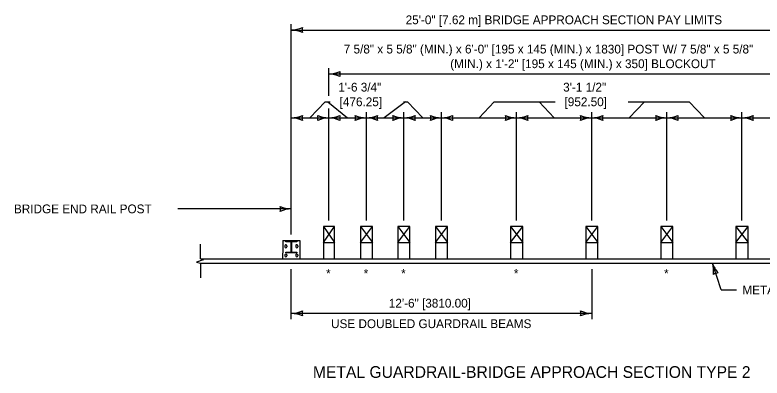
# Model space of a CAD drawing. Extents: x 49991.4 to 50021, y 49987.6 to 50011.4.
# Drawn here: x 50008.83 to 50013.94, y 49992.32 to 49994.8 of the extents above; entities that cross this region are included whole.
import ezdxf

# ---------------------------------------------------------------- set-up
doc = ezdxf.new("R2010")
doc.units = 0
for name, color, linetype in [('Level 1', 7, 'Continuous'), ('Level 2', 7, 'Continuous'), ('Level 3', 7, 'Continuous'), ('Level 6', 7, 'Continuous')]:
    doc.layers.add(name, color=color, linetype=linetype)

msp = doc.modelspace()

# ---------------------------------------------------------------- linework, layer by layer
at = {"layer": 'Level 1'}
for p, q in [((50011.0154, 49993.3576), (50010.9402, 49993.3576)), ((50010.9402, 49993.3576), (50010.9402, 49993.1371)), ((50010.9402, 49993.2474), (50011.0154, 49993.3576)), ((50010.9402, 49993.3576), (50011.0154, 49993.2474)), ((50011.0154, 49993.1371), (50011.0154, 49993.3576)), ((50011.2757, 49993.3576), (50011.1931, 49993.3576)), ((50011.1931, 49993.3576), (50011.1931, 49993.1371)), ((50011.1931, 49993.2474), (50011.2757, 49993.3576)), ((50011.1931, 49993.3576), (50011.2757, 49993.2474)), ((50011.2757, 49993.1371), (50011.2757, 49993.3576)), ((50011.5323, 49993.3576), (50011.4497, 49993.3576)), ((50011.4497, 49993.3576), (50011.4497, 49993.1371)), ((50011.4497, 49993.2474), (50011.5323, 49993.3576)), ((50011.4497, 49993.3576), (50011.5323, 49993.2474)), ((50011.5323, 49993.1371), (50011.5323, 49993.3576)), ((50011.7889, 49993.3576), (50011.7063, 49993.3576)), ((50011.7063, 49993.3576), (50011.7063, 49993.1371)), ((50011.7063, 49993.2474), (50011.7889, 49993.3576)), ((50011.7063, 49993.3576), (50011.7889, 49993.2474)), ((50011.7889, 49993.1371), (50011.7889, 49993.3576)), ((50012.3021, 49993.3576), (50012.2195, 49993.3576)), ((50012.2195, 49993.3576), (50012.2195, 49993.1371)), ((50012.2195, 49993.2474), (50012.3021, 49993.3576)), ((50012.2195, 49993.3576), (50012.3021, 49993.2474)), ((50012.3021, 49993.1371), (50012.3021, 49993.3576)), ((50012.8153, 49993.3576), (50012.7327, 49993.3576)), ((50012.7327, 49993.3576), (50012.7327, 49993.1371)), ((50012.7327, 49993.2474), (50012.8153, 49993.3576)), ((50012.7327, 49993.3576), (50012.8153, 49993.2474)), ((50012.8153, 49993.1371), (50012.8153, 49993.3576)), ((50013.3285, 49993.3576), (50013.2459, 49993.3576)), ((50013.2459, 49993.3576), (50013.2459, 49993.1371)), ((50013.2459, 49993.2474), (50013.3285, 49993.3576)), ((50013.2459, 49993.3576), (50013.3285, 49993.2474)), ((50013.3285, 49993.1371), (50013.3285, 49993.3576)), ((50013.8417, 49993.3576), (50013.7591, 49993.3576)), ((50013.7591, 49993.3576), (50013.7591, 49993.1371)), ((50013.7591, 49993.2474), (50013.8417, 49993.3576)), ((50013.7591, 49993.3576), (50013.8417, 49993.2474)), ((50013.8417, 49993.1371), (50013.8417, 49993.3576)), ((50010.6638, 49993.2621), (50010.7788, 49993.2621)), ((50010.6638, 49993.2621), (50010.6638, 49993.1765)), ((50010.6832, 49993.2571), (50010.7596, 49993.2571)), ((50010.6832, 49993.2525), (50010.6832, 49993.2571)), ((50010.7159, 49993.2525), (50010.6832, 49993.2525)), ((50010.7198, 49993.1879), (50010.7198, 49993.2477)), ((50010.723, 49993.2477), (50010.723, 49993.1879)), ((50010.7596, 49993.2525), (50010.727, 49993.2525)), ((50010.7596, 49993.2571), (50010.7596, 49993.2525)), ((50010.7788, 49993.2621), (50010.7788, 49993.1765)), ((50010.9402, 49993.2474), (50011.0154, 49993.2474)), ((50011.1931, 49993.2474), (50011.2757, 49993.2474)), ((50011.4497, 49993.2474), (50011.5323, 49993.2474)), ((50011.7063, 49993.2474), (50011.7889, 49993.2474)), ((50012.2195, 49993.2474), (50012.3021, 49993.2474)), ((50012.7327, 49993.2474), (50012.8153, 49993.2474)), ((50013.2459, 49993.2474), (50013.3285, 49993.2474)), ((50013.7591, 49993.2474), (50013.8417, 49993.2474)), ((50010.6774, 49993.226), (50010.6774, 49993.2186)), ((50010.6901, 49993.2259), (50010.6901, 49993.2185)), ((50010.7524, 49993.2259), (50010.7524, 49993.2185)), ((50010.7651, 49993.2259), (50010.7651, 49993.2185)), ((50010.1008, 49993.1371), (50015.1199, 49993.1371)), ((50010.6638, 49993.1371), (50010.6638, 49993.1759)), ((50010.6638, 49993.1371), (50010.7788, 49993.1371)), ((50010.6774, 49993.1634), (50010.6774, 49993.1562)), ((50010.6832, 49993.1785), (50010.6832, 49993.1831)), ((50010.6832, 49993.1831), (50010.7159, 49993.1831)), ((50010.7596, 49993.1785), (50010.6832, 49993.1785)), ((50010.6901, 49993.1634), (50010.6901, 49993.1562)), ((50010.727, 49993.1831), (50010.7596, 49993.1831)), ((50010.7524, 49993.1634), (50010.7524, 49993.1562)), ((50010.7596, 49993.1831), (50010.7596, 49993.1785)), ((50010.7651, 49993.1634), (50010.7651, 49993.1562)), ((50010.7788, 49993.1765), (50010.7788, 49993.1371)), ((50010.1008, 49993.1071), (50015.1199, 49993.1071))]:
    msp.add_line(p, q, dxfattribs=at)
for centre, radius, start, end in [((50010.7149, 49993.2477), 0.00489, 0, 79.0205), ((50010.7279, 49993.2477), 0.00489, 100.9795, 180), ((50010.6838, 49993.2259), 0.00635, 359.9937, 180.0376), ((50010.6838, 49993.2186), 0.00635, 180.0001, 359.9937), ((50010.7149, 49993.1879), 0.00489, 280.9795, 0), ((50010.7279, 49993.1879), 0.00489, 180, 259.0205), ((50010.7588, 49993.2259), 0.00635, 359.9937, 180.0376), ((50010.7588, 49993.2186), 0.00635, 180.0001, 359.9937), ((50010.6838, 49993.1634), 0.00635, 359.9937, 180.0376), ((50010.6838, 49993.1561), 0.00635, 180.0001, 359.9937), ((50010.7588, 49993.1634), 0.00635, 359.9937, 180.0376), ((50010.7588, 49993.1561), 0.00635, 180.0001, 359.9937)]:
    msp.add_arc(centre, radius, start, end, dxfattribs=at)
at = {"layer": 'Level 3'}
for p, q in [((50010.7212, 49993.3021), (50010.7212, 49994.7392)), ((50010.7212, 49994.6992), (50014.8268, 49994.6992)), ((50010.9778, 49994.2492), (50010.978, 49994.4392)), ((50010.978, 49994.3992), (50014.8268, 49994.3992)), ((50010.9523, 49994.2092), (50010.8489, 49994.0992)), ((50010.9523, 49994.2092), (50010.9877, 49994.2092)), ((50010.97, 49994.2092), (50011.1055, 49994.0992)), ((50011.5016, 49994.2092), (50011.3563, 49994.0992)), ((50011.4873, 49994.2092), (50011.5159, 49994.2092)), ((50011.5159, 49994.2092), (50011.6193, 49994.0992)), ((50012.1076, 49994.2092), (50012.0042, 49994.0992)), ((50012.1076, 49994.2092), (50012.5244, 49994.2092)), ((50012.414, 49994.2092), (50012.5174, 49994.0992)), ((50013.0239, 49994.2092), (50013.4404, 49994.2092)), ((50013.134, 49994.2092), (50013.0306, 49994.0992)), ((50013.4404, 49994.2092), (50013.5438, 49994.0992)), ((50010.9778, 49993.3976), (50010.9778, 49994.1629)), ((50011.2344, 49993.3976), (50011.2344, 49994.1392)), ((50011.491, 49993.3976), (50011.491, 49994.1392)), ((50011.7476, 49993.3976), (50011.7476, 49994.1392)), ((50012.2608, 49993.3976), (50012.2608, 49994.1392)), ((50012.774, 49993.3976), (50012.774, 49994.1392)), ((50013.2872, 49993.3976), (50013.2872, 49994.1392)), ((50013.8004, 49993.3976), (50013.8004, 49994.1392)), ((50010.7212, 49994.0992), (50010.9766, 49994.0992)), ((50010.9766, 49994.0992), (50011.2344, 49994.0992)), ((50011.2344, 49994.0992), (50011.491, 49994.0992)), ((50011.491, 49994.0992), (50011.7476, 49994.0992)), ((50011.7476, 49994.0992), (50012.2608, 49994.0992)), ((50012.2608, 49994.0992), (50012.774, 49994.0992)), ((50012.774, 49994.0992), (50013.2872, 49994.0992)), ((50013.2872, 49994.0992), (50013.8004, 49994.0992)), ((50013.8004, 49994.0992), (50014.8268, 49994.0992)), ((50010.7212, 49993.4777), (50009.9462, 49993.4777)), ((50013.6579, 49992.9242), (50013.5984, 49993.1071)), ((50010.7212, 49992.7236), (50010.7212, 49993.0671)), ((50012.7742, 49993.0671), (50012.7742, 49992.7236)), ((50013.6579, 49992.9242), (50013.763, 49992.9242)), ((50012.7742, 49992.7636), (50010.7212, 49992.7636))]:
    msp.add_line(p, q, dxfattribs=at)
for centre, radius, start, end in [((50010.7097, 49994.932), 0.233, 272.8273, 292.0772), ((50010.8494, 49994.6992), 0.0548, 162.1388, 197.8612), ((50010.7121, 49994.4771), 0.2223, 67.456, 87.6395), ((50010.9665, 49994.632), 0.233, 272.8273, 292.0772), ((50011.1062, 49994.3992), 0.0548, 162.1388, 197.8612), ((50010.9688, 49994.1771), 0.2223, 67.456, 87.6395), ((50010.7097, 49994.332), 0.233, 272.8273, 292.0772), ((50010.8494, 49994.0992), 0.0548, 162.1388, 197.8612), ((50010.987, 49994.3214), 0.2223, 247.456, 267.6395), ((50010.8496, 49994.0992), 0.0548, 342.1388, 17.8612), ((50010.9663, 49994.332), 0.233, 272.8273, 292.0772), ((50011.106, 49994.0992), 0.0548, 162.1388, 197.8612), ((50011.2436, 49994.3214), 0.2223, 247.456, 267.6395), ((50011.1062, 49994.0992), 0.0548, 342.1388, 17.8612), ((50011.2229, 49994.332), 0.233, 272.8273, 292.0772), ((50011.3626, 49994.0992), 0.0548, 162.1388, 197.8612), ((50011.5002, 49994.3214), 0.2223, 247.456, 267.6395), ((50011.3628, 49994.0992), 0.0548, 342.1388, 17.8612), ((50011.4795, 49994.332), 0.233, 272.8273, 292.0772), ((50011.6192, 49994.0992), 0.0548, 162.1388, 197.8612), ((50011.7568, 49994.3214), 0.2223, 247.456, 267.6395), ((50011.6194, 49994.0992), 0.0548, 342.1388, 17.8612), ((50011.7361, 49994.332), 0.233, 272.8273, 292.0772), ((50011.8758, 49994.0992), 0.0548, 162.1388, 197.8612), ((50012.27, 49994.3214), 0.2223, 247.456, 267.6395), ((50012.1326, 49994.0992), 0.0548, 342.1388, 17.8612), ((50012.2493, 49994.332), 0.233, 272.8273, 292.0772), ((50012.389, 49994.0992), 0.0548, 162.1388, 197.8612), ((50012.7832, 49994.3214), 0.2223, 247.456, 267.6395), ((50012.6458, 49994.0992), 0.0548, 342.1388, 17.8612), ((50012.7625, 49994.332), 0.233, 272.8273, 292.0772), ((50012.9022, 49994.0992), 0.0548, 162.1388, 197.8612), ((50013.2964, 49994.3214), 0.2223, 247.456, 267.6395), ((50013.159, 49994.0992), 0.0548, 342.1388, 17.8612), ((50013.2757, 49994.332), 0.233, 272.8273, 292.0772), ((50013.4154, 49994.0992), 0.0548, 162.1388, 197.8612), ((50013.8096, 49994.3214), 0.2223, 247.456, 267.6395), ((50013.6722, 49994.0992), 0.0548, 342.1388, 17.8612), ((50013.7889, 49994.332), 0.233, 272.8273, 292.0772), ((50013.9286, 49994.0992), 0.0548, 162.1388, 197.8612), ((50010.7121, 49993.8771), 0.2223, 67.456, 87.6395), ((50010.9893, 49993.8665), 0.233, 92.8273, 112.0772), ((50010.9687, 49993.8771), 0.2223, 67.456, 87.6395), ((50011.2459, 49993.8665), 0.233, 92.8273, 112.0772), ((50011.2253, 49993.8771), 0.2223, 67.456, 87.6395), ((50011.5025, 49993.8665), 0.233, 92.8273, 112.0772), ((50011.4819, 49993.8771), 0.2223, 67.456, 87.6395), ((50011.7591, 49993.8665), 0.233, 92.8273, 112.0772), ((50011.7385, 49993.8771), 0.2223, 67.456, 87.6395), ((50012.2723, 49993.8665), 0.233, 92.8273, 112.0772), ((50012.2517, 49993.8771), 0.2223, 67.456, 87.6395), ((50012.7855, 49993.8665), 0.233, 92.8273, 112.0772), ((50012.7649, 49993.8771), 0.2223, 67.456, 87.6395), ((50013.2987, 49993.8665), 0.233, 92.8273, 112.0772), ((50013.2781, 49993.8771), 0.2223, 67.456, 87.6395), ((50013.8119, 49993.8665), 0.233, 92.8273, 112.0772), ((50013.7913, 49993.8771), 0.2223, 67.456, 87.6395), ((50010.7304, 49993.6999), 0.2223, 247.456, 267.6395), ((50010.593, 49993.4777), 0.0548, 342.1388, 17.8612), ((50010.7327, 49993.245), 0.233, 92.8273, 112.0772), ((50013.3843, 49993.0471), 0.2223, 355.4765, 15.66), ((50013.8162, 49993.1901), 0.233, 200.8478, 220.0976), ((50013.6381, 49992.9852), 0.0548, 90.1593, 125.8816), ((50010.7097, 49992.9964), 0.233, 272.8273, 292.0772), ((50010.8494, 49992.7636), 0.0548, 162.1388, 197.8612), ((50012.7834, 49992.9858), 0.2223, 247.456, 267.6395), ((50012.646, 49992.7636), 0.0548, 342.1388, 17.8612), ((50010.7121, 49992.5415), 0.2223, 67.456, 87.6395), ((50012.7857, 49992.5309), 0.233, 92.8273, 112.0772)]:
    msp.add_arc(centre, radius, start, end, dxfattribs=at)
at = {"layer": 'Level 6'}
for p, q in [((50010.1008, 49993.1371), (50010.1008, 49993.2371)), ((50010.1008, 49993.1371), (50010.1191, 49993.1306)), ((50010.1191, 49993.1306), (50010.0747, 49993.1148)), ((50010.0747, 49993.1148), (50010.1008, 49993.1071)), ((50010.1008, 49993.1071), (50010.1008, 49993.0071))]:
    msp.add_line(p, q, dxfattribs=at)

# ---------------------------------------------------------------- texts
at = {"layer": 'Level 2'}
for s, height, p in [('25\'-0" [7.62 m] BRIDGE APPROACH SECTION PAY LIMITS', 0.06, (50011.5027, 49994.7392)), ('7 5/8" x 5 5/8" (MIN.) x 6\'-0" [195 x 145 (MIN.) x 1830] POST W/ 7 5/8" x 5 5/8" ', 0.06, (50011.0796, 49994.5392)), ('(MIN.) x 1\'-2" [195 x 145 (MIN.) x 350] BLOCKOUT ', 0.06, (50011.8071, 49994.4392)), ('1\'-6 3/4"', 0.06, (50011.0423, 49994.2792)), ('3\'-1 1/2"', 0.06, (50012.5789, 49994.2792)), ('[476.25]', 0.06, (50011.0516, 49994.1792)), ('[952.50]', 0.06, (50012.5882, 49994.1792)), ('BRIDGE END RAIL POST', 0.06, (50008.8266, 49993.4477)), ('*', 0.06, (50010.9588, 49993.0071)), ('*', 0.06, (50011.2154, 49993.0071)), ('*', 0.06, (50011.472, 49993.0071)), ('*', 0.06, (50012.2418, 49993.0071)), ('*', 0.06, (50013.2682, 49993.0071)), ('METAL GUARDRAIL', 0.06, (50013.803, 49992.8942)), ('12\'-6" [3810.00]', 0.06, (50011.3877, 49992.8036)), ('USE DOUBLED GUARDRAIL BEAMS', 0.06, (50010.9929, 49992.6636)), ('METAL GUARDRAIL-BRIDGE APPROACH SECTION TYPE 2', 0.08, (50010.8689, 49992.3235))]:
    msp.add_text(s, height=height, dxfattribs=at).set_placement(p)

doc.saveas('drawing.dxf')
